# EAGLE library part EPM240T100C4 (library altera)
EPM240T100 Low-cost, low-power CPLD Auto generated by make-symbol-device-package-bsdl.ulp Rev. 35 Source: www.altera.com .. epm240-io.txt
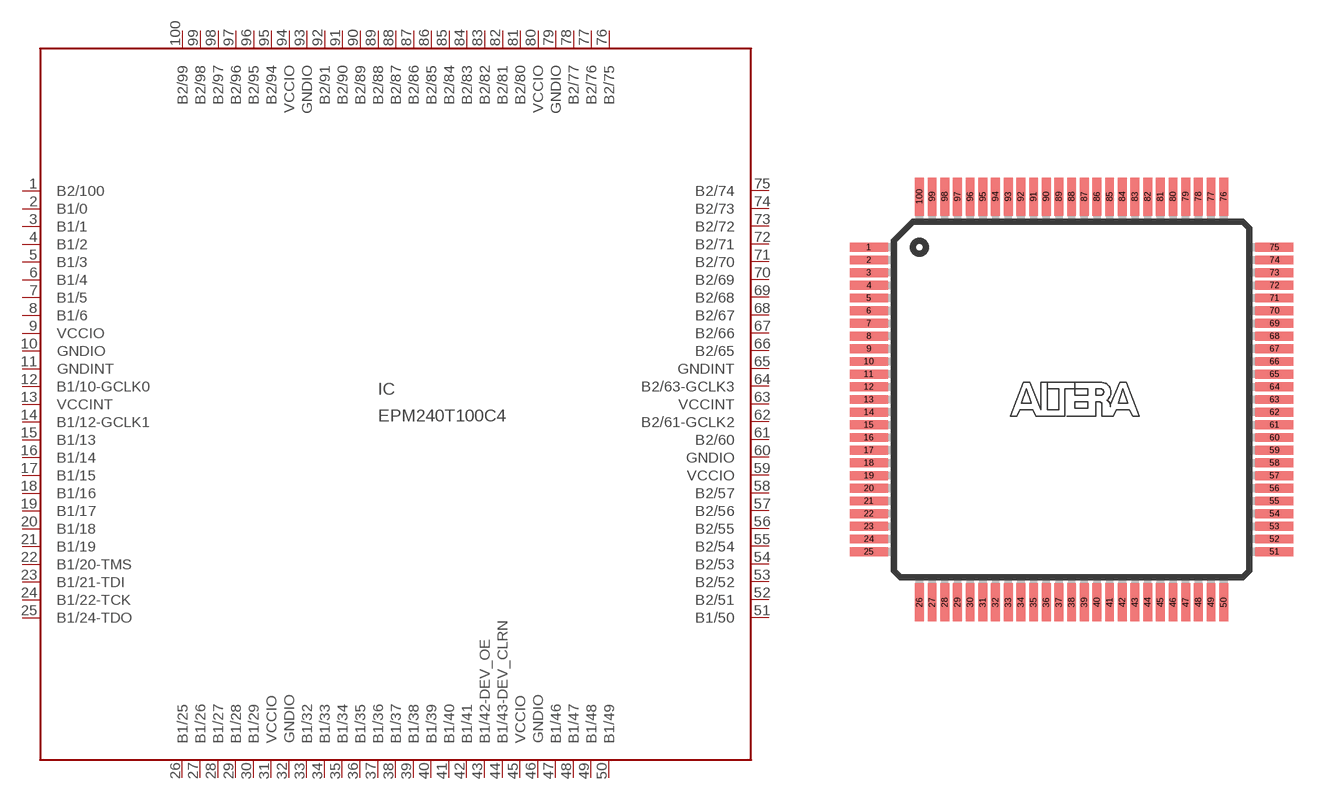
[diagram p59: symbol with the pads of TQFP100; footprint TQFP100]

Designator prefix IC

## EPM240T100C4 (MPN: EPM240T100C4; OC_FARNELL: 1453502; OC_NEWARK: 51R9357)  [TQFP100]
1  B2/100
2  B1/0
3  B1/1
4  B1/2
5  B1/3
6  B1/4
7  B1/5
8  B1/6
9  VCCIO  pwr
10  GNDIO  pwr
11  GNDINT  pwr
12  B1/10-GCLK0
13  VCCINT  pwr
14  B1/12-GCLK1
15  B1/13
16  B1/14
17  B1/15
18  B1/16
19  B1/17
20  B1/18
21  B1/19
22  B1/20-TMS  in
23  B1/21-TDI  in
24  B1/22-TCK  in
25  B1/24-TDO  out
26  B1/25
27  B1/26
28  B1/27
29  B1/28
30  B1/29
31  VCCIO  pwr
32  GNDIO  pwr
33  B1/32
34  B1/33
35  B1/34
36  B1/35
37  B1/36
38  B1/37
39  B1/38
40  B1/39
41  B1/40
42  B1/41
43  B1/42-DEV_OE
44  B1/43-DEV_CLRN
45  VCCIO  pwr
46  GNDIO  pwr
47  B1/46
48  B1/47
49  B1/48
50  B1/49
51  B1/50
52  B2/51
53  B2/52
54  B2/53
55  B2/54
56  B2/55
57  B2/56
58  B2/57
59  VCCIO  pwr
60  GNDIO  pwr
61  B2/60
62  B2/61-GCLK2
63  VCCINT  pwr
64  B2/63-GCLK3
65  GNDINT  pwr
66  B2/65
67  B2/66
68  B2/67
69  B2/68
70  B2/69
71  B2/70
72  B2/71
73  B2/72
74  B2/73
75  B2/74
76  B2/75
77  B2/76
78  B2/77
79  GNDIO  pwr
80  VCCIO  pwr
81  B2/80
82  B2/81
83  B2/82
84  B2/83
85  B2/84
86  B2/85
87  B2/86
88  B2/87
89  B2/88
90  B2/89
91  B2/90
92  B2/91
93  GNDIO  pwr
94  VCCIO  pwr
95  B2/94
96  B2/95
97  B2/96
98  B2/97
99  B2/98
100  B2/99

## Footprint TQFP100 (pad centres in mm)
Plastic Thin Quad Flat Pack
smd 1.5 x 0.35: 1 -8,6; 2 -8,5.5; 3 -8,5; 4 -8,4.5; 5 -8,4; 6 -8,3.5; 7 -8,3; 8 -8,2.5; 9 -8,2; 10 -8,1.5; 11 -8,1; 12 -8,0.5; 13 -8,0; 14 -8,-0.5; 15 -8,-1; 16 -8,-1.5; 17 -8,-2; 18 -8,-2.5; 19 -8,-3; 20 -8,-3.5; 21 -8,-4; 22 -8,-4.5; 23 -8,-5; 24 -8,-5.5; 25 -8,-6; 51 8,-6; 52 8,-5.5; 53 8,-5; 54 8,-4.5; 55 8,-4; 56 8,-3.5; 57 8,-3; 58 8,-2.5; 59 8,-2; 60 8,-1.5; 61 8,-1; 62 8,-0.5; 63 8,0; 64 8,0.5; 65 8,1; 66 8,1.5; 67 8,2; 68 8,2.5; 69 8,3; 70 8,3.5; 71 8,4; 72 8,4.5; 73 8,5; 74 8,5.5; 75 8,6
smd 0.35 x 1.5: 26 -6,-8; 27 -5.5,-8; 28 -5,-8; 29 -4.5,-8; 30 -4,-8; 31 -3.5,-8; 32 -3,-8; 33 -2.5,-8; 34 -2,-8; 35 -1.5,-8; 36 -1,-8; 37 -0.5,-8; 38 0,-8; 39 0.5,-8; 40 1,-8; 41 1.5,-8; 42 2,-8; 43 2.5,-8; 44 3,-8; 45 3.5,-8; 46 4,-8; 47 4.5,-8; 48 5,-8; 49 5.5,-8; 50 6,-8; 76 6,8; 77 5.5,8; 78 5,8; 79 4.5,8; 80 4,8; 81 3.5,8; 82 3,8; 83 2.5,8; 84 2,8; 85 1.5,8; 86 1,8; 87 0.5,8; 88 0,8; 89 -0.5,8; 90 -1,8; 91 -1.5,8; 92 -2,8; 93 -2.5,8; 94 -3,8; 95 -3.5,8; 96 -4,8; 97 -4.5,8; 98 -5,8; 99 -5.5,8; 100 -6,8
